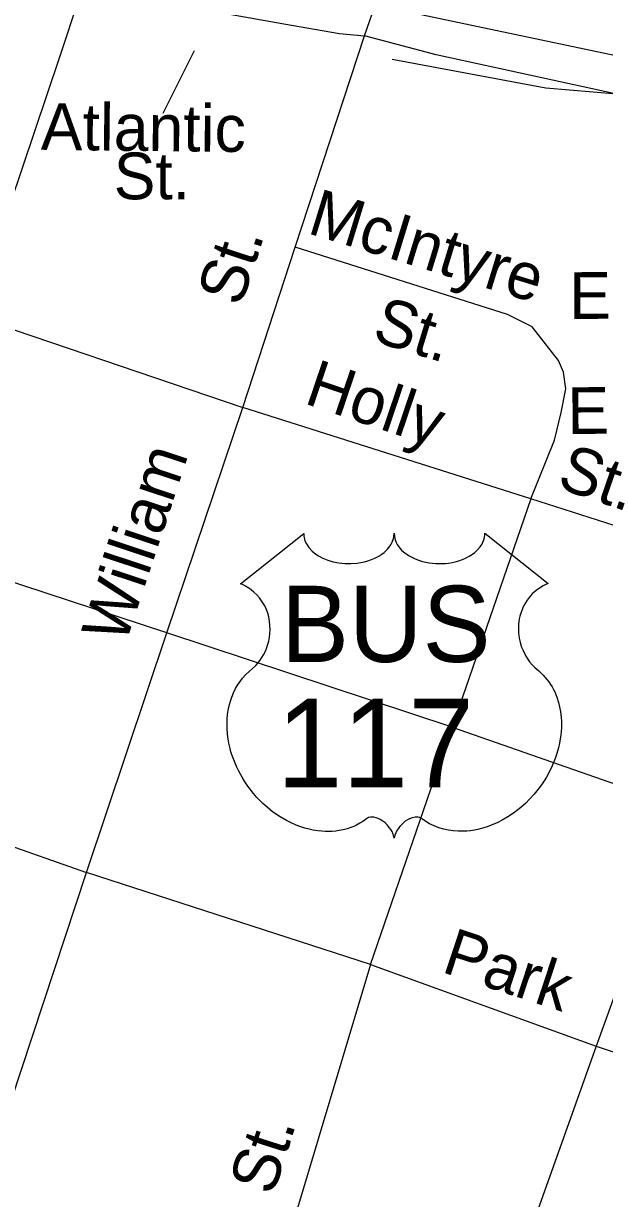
# Model space of a CAD drawing. Extents: x 2260773 to 2342389, y 552869 to 618546.
# Drawn here: x 2300461 to 2301642, y 596757 to 599147 of the extents above; entities that cross this region are included whole.
import ezdxf

# ---------------------------------------------------------------- set-up
doc = ezdxf.new("R2010")
doc.units = 0
for name, color, linetype in [('Exist Railroad Mainline', 7, 'Continuous'), ('Exist Railroad Siding', 7, 'Continuous'), ('Exist Road Non-System Type 51', 7, 'Continuous'), ('Exist Road Non-System Type 51 Label', 7, 'Continuous'), ('Exist Road Primary US Attributed', 7, 'Continuous'), ('Exist Road Primary US Label', 7, 'Continuous'), ('Exist Road Primary US Shield CELL', 7, 'Continuous'), ('Exist Road Primary US Shield Number Label', 7, 'Continuous'), ('Exist Road Secondary Type 51 Attributed', 7, 'Continuous')]:
    doc.layers.add(name, color=color, linetype=linetype)

msp = doc.modelspace()

# ---------------------------------------------------------------- linework, layer by layer
at = {"layer": 'Exist Railroad Mainline'}
for points in [[(2300273.9, 599141.4), (2300333.5, 599166.1), (2300401.4, 599190.8), (2300467.1, 599201.5), (2300559.1, 599202.4), (2300574.4, 599201.3), (2300659, 599195.4), (2300765.1, 599184.7), (2300879.3, 599165.9), (2301005.4, 599143.2), (2301103.5, 599126.4), (2301154.3, 599121.4)], [(2301666.7, 599002.6), (2301300, 599082.6), (2301154.3, 599121.4)]]:
    msp.add_lwpolyline(points, dxfattribs=at)
at = {"layer": 'Exist Railroad Siding'}
msp.add_lwpolyline([(2301666.7, 599002.6), (2301522.5, 599014.9), (2301210.1, 599073.5)], dxfattribs=at)
at = {"layer": 'Exist Road Non-System Type 51'}
for p, q in [((2300356.3, 598552.4), (2300906.4, 598365.8)), ((2301491.9, 598180), (2300906.4, 598365.8)), ((2301491.9, 598180), (2301332.1, 597716.1)), ((2301975.4, 598025.6), (2301491.9, 598180)), ((2300752.1, 597907.5), (2300203.6, 598087.8)), ((2301332.1, 597716.1), (2300752.1, 597907.5)), ((2301166.4, 597233.2), (2301332.1, 597716.1)), ((2301332.1, 597716.1), (2301799.6, 597552.4)), ((2300048, 597611.5), (2300588.8, 597420.3)), ((2301799.6, 597552.4), (2301625.3, 597067.2)), ((2301166.4, 597233.2), (2300588.8, 597420.3)), ((2301166.4, 597233.2), (2300974.9, 596596.2)), ((2301166.4, 597233.2), (2301625.3, 597067.2)), ((2301625.3, 597067.2), (2301406.1, 596455)), ((2301625.3, 597067.2), (2302511.7, 596768.7))]:
    msp.add_line(p, q, dxfattribs=at)
for points in [[(2300574.4, 599201.3), (2300534.2, 599078.4), (2300356.3, 598552.4)], [(2301491.9, 598180), (2301540.3, 598299.5), (2301553.6, 598355.6), (2301563.1, 598403.6), (2301558.7, 598437.7), (2301548.5, 598461.5), (2301495, 598529.6), (2301444.7, 598554.8), (2301013.4, 598691.8)]]:
    msp.add_lwpolyline(points, dxfattribs=at)
at = {"layer": 'Exist Road Non-System Type 51 Label'}
msp.add_lwpolyline([(2300744.7, 598964.4), (2300808.4, 599091.8)], dxfattribs=at)
at = {"layer": 'Exist Road Primary US Attributed'}
msp.add_line((2301154.3, 599121.4), (2301176, 599183.7), dxfattribs=at)
msp.add_lwpolyline([(2300273.8, 596473.9), (2300435.5, 596955.8), (2300588.8, 597420.3), (2300752.1, 597907.5), (2300906.4, 598365.8), (2301013.4, 598691.8), (2301154.3, 599121.4)], dxfattribs=at)
at = {"layer": 'Exist Road Primary US Shield CELL'}
for p, q in [((2300901.9, 598007.3), (2301030.5, 598109.7)), ((2301030.5, 598109.7), (2301030.9, 598104.4)), ((2301030.9, 598104.4), (2301032.1, 598098.1)), ((2301210.5, 598091.7), (2301213.2, 598099.5)), ((2301213.2, 598099.5), (2301214, 598102.9)), ((2301214, 598102.9), (2301214.5, 598110)), ((2301214.5, 598110), (2301215, 598104)), ((2301215, 598104), (2301215.6, 598100.3)), ((2301215.6, 598100.3), (2301216.6, 598096.7)), ((2301396.6, 598096.7), (2301397.8, 598101.8)), ((2301397.8, 598101.8), (2301398.4, 598106.3)), ((2301398.4, 598106.3), (2301398.6, 598110.1)), ((2301398.6, 598110.1), (2301527.2, 598007.7)), ((2301032.1, 598098.1), (2301033.1, 598094.8)), ((2301033.1, 598094.8), (2301036.1, 598088.6)), ((2301036.1, 598088.6), (2301041, 598081.2)), ((2301041, 598081.2), (2301047.8, 598074)), ((2301194, 598071), (2301200.9, 598077.5)), ((2301200.9, 598077.5), (2301206.3, 598084.3)), ((2301206.3, 598084.3), (2301208.6, 598088.1)), ((2301208.6, 598088.1), (2301210.5, 598091.7)), ((2301216.6, 598096.7), (2301218.1, 598092.8)), ((2301218.1, 598092.8), (2301220.8, 598087.3)), ((2301220.8, 598087.3), (2301223.9, 598082.7)), ((2301223.9, 598082.7), (2301229.6, 598076)), ((2301229.6, 598076), (2301233.2, 598072.6)), ((2301378.3, 598071.3), (2301383.9, 598076.5)), ((2301383.9, 598076.5), (2301389.2, 598082.7)), ((2301389.2, 598082.7), (2301392.3, 598087.2)), ((2301392.3, 598087.2), (2301394.5, 598091.8)), ((2301394.5, 598091.8), (2301396.6, 598096.7)), ((2301047.8, 598074), (2301055.4, 598067.7)), ((2301055.4, 598067.7), (2301060.6, 598064.4)), ((2301060.6, 598064.4), (2301069.4, 598059.6)), ((2301069.4, 598059.6), (2301079.3, 598055.5)), ((2301079.3, 598055.5), (2301090.4, 598052.3)), ((2301090.4, 598052.3), (2301101.7, 598050)), ((2301139.5, 598049.4), (2301154.1, 598052.2)), ((2301154.1, 598052.2), (2301160.9, 598053.9)), ((2301160.9, 598053.9), (2301168.4, 598056.5)), ((2301168.4, 598056.5), (2301175.4, 598059.4)), ((2301175.4, 598059.4), (2301183.1, 598063.5)), ((2301183.1, 598063.5), (2301189.2, 598067.5)), ((2301189.2, 598067.5), (2301194, 598071)), ((2301233.2, 598072.6), (2301236.4, 598070)), ((2301236.4, 598070), (2301245.2, 598064)), ((2301245.2, 598064), (2301255.4, 598058.8)), ((2301255.4, 598058.8), (2301260.4, 598056.6)), ((2301260.4, 598056.6), (2301265.6, 598054.8)), ((2301265.6, 598054.8), (2301272.1, 598052.8)), ((2301272.1, 598052.8), (2301278.9, 598051.2)), ((2301278.9, 598051.2), (2301285.5, 598050.1)), ((2301325.1, 598049.6), (2301332.4, 598050.8)), ((2301332.4, 598050.8), (2301338.3, 598052.1)), ((2301338.3, 598052.1), (2301346, 598054.2)), ((2301346, 598054.2), (2301353, 598056.7)), ((2301353, 598056.7), (2301359.1, 598059.3)), ((2301359.1, 598059.3), (2301367.1, 598063.5)), ((2301367.1, 598063.5), (2301373.6, 598067.5)), ((2301373.6, 598067.5), (2301378.3, 598071.3)), ((2301101.7, 598050), (2301114.1, 598048.6)), ((2301114.1, 598048.6), (2301126.3, 598048.4)), ((2301126.3, 598048.4), (2301139.5, 598049.4)), ((2301285.5, 598050.1), (2301292.4, 598049.1)), ((2301292.4, 598049.1), (2301299.4, 598048.5)), ((2301299.4, 598048.5), (2301305.1, 598048.4)), ((2301305.1, 598048.4), (2301312.1, 598048.5)), ((2301312.1, 598048.5), (2301318.5, 598048.9)), ((2301318.5, 598048.9), (2301325.1, 598049.6)), ((2300905.9, 598005.7), (2300901.9, 598007.3)), ((2300912.2, 598002.6), (2300905.9, 598005.7)), ((2301517.1, 598003.1), (2301511.6, 597999.8)), ((2301524.1, 598006.5), (2301517.1, 598003.1)), ((2301527.2, 598007.7), (2301524.1, 598006.5)), ((2300918.7, 597998.6), (2300912.2, 598002.6)), ((2300923.9, 597994.9), (2300918.7, 597998.6)), ((2300929.4, 597990.6), (2300923.9, 597994.9)), ((2300935.1, 597984.9), (2300929.4, 597990.6)), ((2300940.8, 597978.6), (2300935.1, 597984.9)), ((2301488.6, 597979.2), (2301484.9, 597974.1)), ((2301491.7, 597982.8), (2301488.6, 597979.2)), ((2301495.2, 597986.6), (2301491.7, 597982.8)), ((2301499, 597990.2), (2301495.2, 597986.6)), ((2301502.8, 597993.6), (2301499, 597990.2)), ((2301511.6, 597999.8), (2301502.8, 597993.6)), ((2300946.2, 597970.7), (2300940.8, 597978.6)), ((2300951.2, 597962.3), (2300946.2, 597970.7)), ((2300954.1, 597956.1), (2300951.2, 597962.3)), ((2300957.3, 597947.6), (2300954.1, 597956.1)), ((2301475.9, 597958.3), (2301471.9, 597947.9)), ((2301478.3, 597963.2), (2301475.9, 597958.3)), ((2301481.5, 597968.9), (2301478.3, 597963.2)), ((2301484.9, 597974.1), (2301481.5, 597968.9)), ((2300959.3, 597940.1), (2300957.3, 597947.6)), ((2300961, 597931.6), (2300959.3, 597940.1)), ((2300961.9, 597922.7), (2300961, 597931.6)), ((2301468.8, 597935.9), (2301467.3, 597924.4)), ((2301470, 597941.4), (2301468.8, 597935.9)), ((2301471.9, 597947.9), (2301470, 597941.4)), ((2300961.8, 597905.9), (2300962.2, 597915.1)), ((2300962.2, 597915.1), (2300961.9, 597922.7)), ((2301467.3, 597924.4), (2301466.9, 597918.9)), ((2301466.9, 597918.9), (2301466.9, 597913.5)), ((2301466.9, 597913.5), (2301467.2, 597907.8)), ((2301467.2, 597907.8), (2301467.7, 597902.3)), ((2300954.8, 597876), (2300957.8, 597884.6)), ((2300957.8, 597884.6), (2300959.3, 597890.7)), ((2300959.3, 597890.7), (2300960.8, 597898.5)), ((2300960.8, 597898.5), (2300961.8, 597905.9)), ((2301467.7, 597902.3), (2301468.7, 597896.7)), ((2301468.7, 597896.7), (2301469.6, 597891.6)), ((2301469.6, 597891.6), (2301471.2, 597885.5)), ((2301471.2, 597885.5), (2301473.5, 597878.3)), ((2300945.6, 597857.7), (2300948.6, 597862.8)), ((2300948.6, 597862.8), (2300952.5, 597870.4)), ((2300952.5, 597870.4), (2300954.8, 597876)), ((2301473.5, 597878.3), (2301476.3, 597871.4)), ((2301476.3, 597871.4), (2301482.2, 597860.3)), ((2301482.2, 597860.3), (2301489.8, 597848.9)), ((2300925.9, 597834.2), (2300933.3, 597841.5)), ((2300933.3, 597841.5), (2300937.2, 597845.9)), ((2300937.2, 597845.9), (2300941.9, 597852)), ((2300941.9, 597852), (2300945.6, 597857.7)), ((2301489.8, 597848.9), (2301495.2, 597842.5)), ((2301495.2, 597842.5), (2301500.5, 597837)), ((2301500.5, 597837), (2301508.4, 597830.3)), ((2300901.2, 597809), (2300906.2, 597815.4)), ((2300906.2, 597815.4), (2300912.8, 597822.6)), ((2300912.8, 597822.6), (2300919.6, 597829.1)), ((2300919.6, 597829.1), (2300925.9, 597834.2)), ((2301508.4, 597830.3), (2301512.7, 597826.5)), ((2301512.7, 597826.5), (2301517.6, 597821.6)), ((2301517.6, 597821.6), (2301525.7, 597812.2)), ((2301525.7, 597812.2), (2301529, 597807.8)), ((2300887.8, 597785.8), (2300892.1, 597794.3)), ((2300892.1, 597794.3), (2300896.1, 597801.4)), ((2300896.1, 597801.4), (2300901.2, 597809)), ((2301529, 597807.8), (2301532.3, 597802.9)), ((2301532.3, 597802.9), (2301535.3, 597797.8)), ((2301535.3, 597797.8), (2301538.3, 597792.3)), ((2301538.3, 597792.3), (2301540.8, 597787.5)), ((2300879.6, 597762.2), (2300881.5, 597768.8)), ((2300881.5, 597768.8), (2300884.2, 597776.9)), ((2300884.2, 597776.9), (2300887.8, 597785.8)), ((2301540.8, 597787.5), (2301545.3, 597776.5)), ((2301545.3, 597776.5), (2301548.6, 597765.8)), ((2301548.6, 597765.8), (2301550.1, 597760.2)), ((2300874.9, 597732.2), (2300875.9, 597742.3)), ((2300875.9, 597742.3), (2300877.6, 597753)), ((2300877.6, 597753), (2300879.6, 597762.2)), ((2301550.1, 597760.2), (2301552.5, 597747.6)), ((2301552.5, 597747.6), (2301553.4, 597741.3)), ((2301553.4, 597741.3), (2301554.4, 597729)), ((2300874.6, 597723.5), (2300874.9, 597732.2)), ((2300874.7, 597713.1), (2300874.6, 597723.5)), ((2301554.4, 597729), (2301554.4, 597714.1)), ((2300875.5, 597701.8), (2300874.7, 597713.1)), ((2300877, 597691.1), (2300875.5, 597701.8)), ((2301553.3, 597700), (2301550.6, 597683.5)), ((2301554.4, 597714.1), (2301553.3, 597700)), ((2300878.5, 597683.3), (2300877, 597691.1)), ((2300880.9, 597672.3), (2300878.5, 597683.3)), ((2300882.6, 597666), (2300880.9, 597672.3)), ((2301548.4, 597673.6), (2301545.1, 597662.2)), ((2301550.6, 597683.5), (2301548.4, 597673.6)), ((2300885.8, 597656.1), (2300882.6, 597666)), ((2300889.6, 597645.7), (2300885.8, 597656.1)), ((2300894.5, 597634.3), (2300889.6, 597645.7)), ((2301541.8, 597652.2), (2301535.9, 597637.5)), ((2301545.1, 597662.2), (2301541.8, 597652.2)), ((2300898.3, 597626.4), (2300894.5, 597634.3)), ((2300905.1, 597614), (2300898.3, 597626.4)), ((2301530.7, 597626.9), (2301523.9, 597614.4)), ((2301535.9, 597637.5), (2301530.7, 597626.9)), ((2300909.8, 597606.2), (2300905.1, 597614)), ((2300917, 597595.7), (2300909.8, 597606.2)), ((2301513.9, 597598.9), (2301507.2, 597589.6)), ((2301519.3, 597606.9), (2301513.9, 597598.9)), ((2301523.9, 597614.4), (2301519.3, 597606.9)), ((2300928.3, 597581.1), (2300917, 597595.7)), ((2300935.4, 597572.9), (2300928.3, 597581.1)), ((2300947.7, 597560.5), (2300935.4, 597572.9)), ((2301499.3, 597579.7), (2301489.8, 597569.3)), ((2301507.2, 597589.6), (2301499.3, 597579.7)), ((2300956, 597553), (2300947.7, 597560.5)), ((2300967.3, 597543.8), (2300956, 597553)), ((2301472.1, 597552.7), (2301466, 597547.6)), ((2301482.1, 597561.6), (2301472.1, 597552.7)), ((2301489.8, 597569.3), (2301482.1, 597561.6)), ((2300982.4, 597533.4), (2300967.3, 597543.8)), ((2300995.2, 597526), (2300982.4, 597533.4)), ((2301003.3, 597521.8), (2300995.2, 597526)), ((2301156.3, 597527.9), (2301150.8, 597524.1)), ((2301162.1, 597532.1), (2301156.3, 597527.9)), ((2301166.4, 597533.1), (2301162.1, 597532.1)), ((2301169.5, 597533.1), (2301166.4, 597533.1)), ((2301173.3, 597532.8), (2301169.5, 597533.1)), ((2301178, 597531.7), (2301173.3, 597532.8)), ((2301181.8, 597530.2), (2301178, 597531.7)), ((2301185.9, 597528.1), (2301181.8, 597530.2)), ((2301191.1, 597525), (2301185.9, 597528.1)), ((2301195.9, 597521), (2301191.1, 597525)), ((2301241.8, 597527.6), (2301237, 597524.5)), ((2301245.3, 597529.5), (2301241.8, 597527.6)), ((2301251.3, 597531.8), (2301245.3, 597529.5)), ((2301257, 597533.1), (2301251.3, 597531.8)), ((2301263.2, 597532.7), (2301257, 597533.1)), ((2301265.8, 597532.1), (2301263.2, 597532.7)), ((2301270.4, 597529.6), (2301265.8, 597532.1)), ((2301286.3, 597519.6), (2301270.4, 597529.6)), ((2301433.8, 597526.4), (2301423.8, 597521.4)), ((2301445.5, 597533.2), (2301433.8, 597526.4)), ((2301457.3, 597541.1), (2301445.5, 597533.2)), ((2301466, 597547.6), (2301457.3, 597541.1)), ((2301015, 597516.7), (2301003.3, 597521.8)), ((2301024.4, 597513.1), (2301015, 597516.7)), ((2301033.1, 597510.4), (2301024.4, 597513.1)), ((2301041.6, 597508.1), (2301033.1, 597510.4)), ((2301049.7, 597506.3), (2301041.6, 597508.1)), ((2301059.4, 597504.9), (2301049.7, 597506.3)), ((2301067.2, 597504.2), (2301059.4, 597504.9)), ((2301074, 597503.6), (2301067.2, 597504.2)), ((2301081.2, 597503.6), (2301074, 597503.6)), ((2301088.1, 597503.8), (2301081.2, 597503.6)), ((2301095.8, 597504.5), (2301088.1, 597503.8)), ((2301102.9, 597505.6), (2301095.8, 597504.5)), ((2301111, 597507.2), (2301102.9, 597505.6)), ((2301118.9, 597509.3), (2301111, 597507.2)), ((2301126.2, 597511.7), (2301118.9, 597509.3)), ((2301132.4, 597514.1), (2301126.2, 597511.7)), ((2301137.7, 597516.6), (2301132.4, 597514.1)), ((2301144.8, 597520.4), (2301137.7, 597516.6)), ((2301150.8, 597524.1), (2301144.8, 597520.4)), ((2301200, 597517.2), (2301195.9, 597521)), ((2301204.4, 597512), (2301200, 597517.2)), ((2301207.3, 597508), (2301204.4, 597512)), ((2301210, 597503.4), (2301207.3, 597508)), ((2301212.4, 597498.1), (2301210, 597503.4)), ((2301219.1, 597504.1), (2301217.5, 597500.8)), ((2301223.6, 597511.2), (2301219.1, 597504.1)), ((2301225.9, 597513.9), (2301223.6, 597511.2)), ((2301229, 597517.4), (2301225.9, 597513.9)), ((2301233.4, 597521.6), (2301229, 597517.4)), ((2301237, 597524.5), (2301233.4, 597521.6)), ((2301295.7, 597515), (2301286.3, 597519.6)), ((2301305, 597511.3), (2301295.7, 597515)), ((2301315.2, 597508.3), (2301305, 597511.3)), ((2301325, 597506.2), (2301315.2, 597508.3)), ((2301334.5, 597504.9), (2301325, 597506.2)), ((2301344.4, 597504.1), (2301334.5, 597504.9)), ((2301354.4, 597504.1), (2301344.4, 597504.1)), ((2301361.9, 597504.6), (2301354.4, 597504.1)), ((2301369.5, 597505.3), (2301361.9, 597504.6)), ((2301377.7, 597506.5), (2301369.5, 597505.3)), ((2301384.7, 597508), (2301377.7, 597506.5)), ((2301403.6, 597513.2), (2301384.7, 597508)), ((2301415, 597517.6), (2301403.6, 597513.2)), ((2301423.8, 597521.4), (2301415, 597517.6)), ((2301214.4, 597490.1), (2301212.4, 597498.1)), ((2301215.9, 597496.4), (2301214.4, 597490.1)), ((2301217.5, 597500.8), (2301215.9, 597496.4))]:
    msp.add_line(p, q, dxfattribs=at)
at = {"layer": 'Exist Road Secondary Type 51 Attributed'}
msp.add_lwpolyline([(2304346.9, 598464.1), (2304151.8, 598509.1), (2304039.3, 598533), (2303660, 598625.1), (2303191.8, 598726.9), (2302889.2, 598795.5), (2302719.8, 598839.3), (2302587.3, 598872.9), (2302225.3, 598962.7), (2301176, 599183.7)], dxfattribs=at)

# ---------------------------------------------------------------- texts
at = {"layer": 'Exist Road Non-System Type 51 Label'}
for s, rotation, p in [('Atlantic', 359.3785, (2300495.7, 598889.8)), ('St.', 359.9424, (2300644.3, 598789.2)), ('McIntyre', 342.9351, (2301035.4, 598720.9)), ('Edwards', 0.1946, (2301570.5, 598545.9)), ('St.', 342.9351, (2301166.7, 598502.1)), ('Holly', 341.3168, (2301028.8, 598374.9)), ('Eunice', 0.4687, (2301567, 598311.8)), ('St.', 341.0234, (2301542.2, 598203.9)), ('Park', 341.7174, (2301308.1, 597218.7)), ('St.', 72.1918, (2300967.9, 596761))]:
    msp.add_text(s, height=95, rotation=rotation, dxfattribs=at).set_placement(p)
at = {"layer": 'Exist Road Primary US Label'}
for s, rotation, p in [('St.', 71.84, (2300902.6, 598568.5)), ('William', 71.6417, (2300667.5, 597881.5))]:
    msp.add_text(s, height=95, rotation=rotation, dxfattribs=at).set_placement(p)
at = {"layer": 'Exist Road Primary US Shield Number Label'}
for s, height, p in [('BUS', 155, (2300984.2, 597848.4)), ('117', 180, (2300975.3, 597593.5))]:
    msp.add_text(s, height=height, dxfattribs=at).set_placement(p)

doc.saveas('drawing.dxf')
